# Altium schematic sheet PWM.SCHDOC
size A4; Organization: Altium Limited; Address1: L3, 12a Rodborough Rd; Address2: Frenchs Forest; Address3: NSW; Address4: Australia 2086; DocumentNumber: 6; SheetNumber: 6; SheetTotal: 6
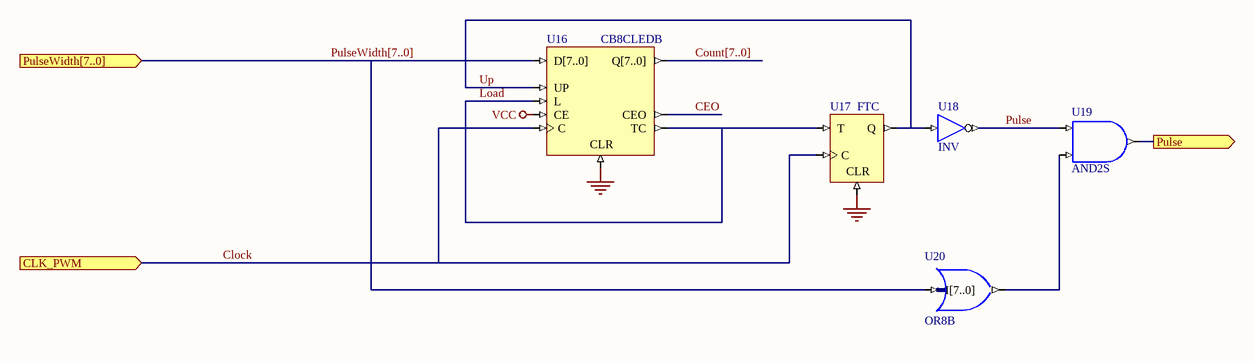
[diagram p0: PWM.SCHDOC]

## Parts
U16  CB8CLEDB
U17  FTC
U18  INV
U19  AND2S
U20  OR8B

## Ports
CLK_PWM (in), Pulse (out), PulseWidth[7..0] (in)

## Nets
GND: U16.CLR U17.CLR
VCC: U16.CE
CEO: U16.CEO
Clock: U16.C U17.C ; port CLK_PWM
Load: U16.L U16.TC U17.T
Pulse: U18.O U19.I0
Pulse: U19.O ; port Pulse  [a separate net that carries the same name]
Up: U16.UP U17.Q U18.I
NetU19_I1: U19.I1 U20.O

Not connected (* = marked no-connect by the designer): U16 D[7..0] Q[7..0]; U20 I[7..0]

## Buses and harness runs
bus Count[7..0]
bus PulseWidth[7..0] = port PulseWidth[7..0]

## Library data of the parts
U16 = CB8CLEDB: 8-Bit Loadable Cascadable Bidirectional Binary Counter with Clock Enable and Asynchronous Clear, Bus Version; ArchiveName: GENERIC
U17 = FTC: Toggle Flip-Flop with Toggle Enable and Asynchronous Clear; ArchiveName: GENERIC
U18 = INV: Inverter; ArchiveName: GENERIC
U19 = AND2S: 2-Input AND Gate, Single Pin Version; Xilinx Equivalent: AND2; ArchiveName: GENERIC
U20 = OR8B: 8-Input OR Gate, Bus Version; ArchiveName: GENERIC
